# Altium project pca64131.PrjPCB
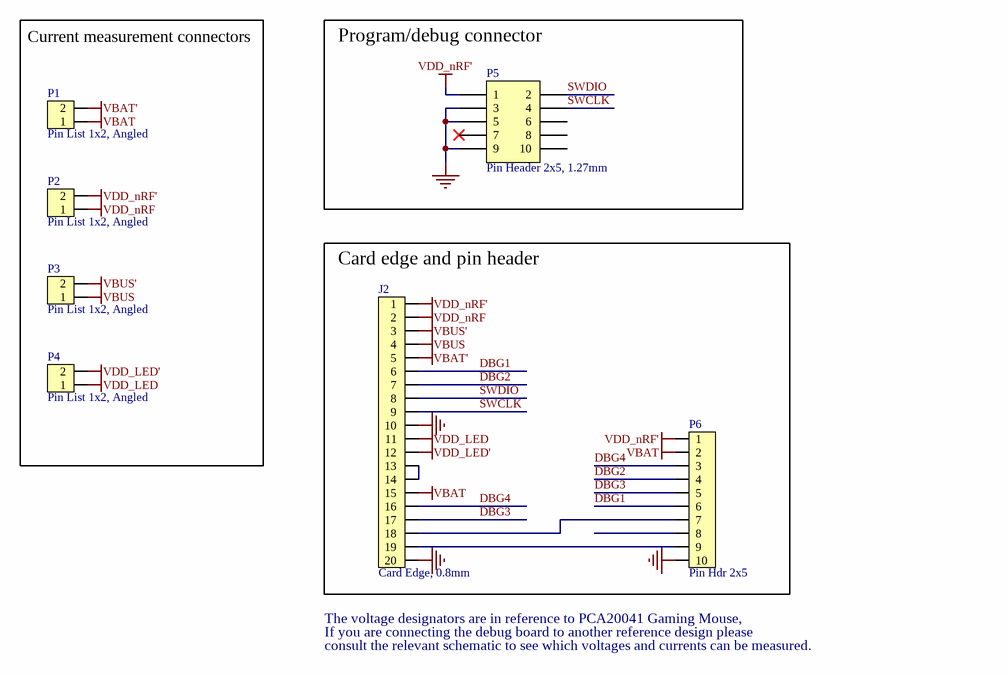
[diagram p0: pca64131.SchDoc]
SurfaceFinish: ENIG Gold; SoldermaskColor: Blue; SilkscreenColor: White; Revision: 0.4.1; ProjectNumber: 4456; ProjectName: nRF52 Desktop; PCBStackup: 2004; PCBRevision: 0017MASI; PCBNumber: 400391; PCAName: PCA64131; Organization: Nordic Semiconductor; NrOfLayers: 2; BoardTitle: nRF52 Desktop Debug Board; BoardThickness: 1.0mm; Author: RUBR/MASI
1 sheet, 7 parts. Net scope: global (net labels, ports and power ports of the same name join across sheets).
Board file: 400391.PcbDoc

## Sheet pca64131.SchDoc: =BoardTitle
size A4; Organization: Nordic Semiconductor; Revision: 0.4.1; SheetNumber: 1; SheetTotal: 1; Author: RUBR/MASI; CompanyName: Nordic Semiconductor; DrawnBy: RUBR/MASI

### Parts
J2  Card Edge, 0.8mm  [10056847-101LF Mating Board]
P1  Pin List 1x2, Angled  [LIST_ANG_1x2-SMD-2.54MM]
P2  Pin List 1x2, Angled  [LIST_ANG_1x2-SMD-2.54MM]
P3  Pin List 1x2, Angled  [LIST_ANG_1x2-SMD-2.54MM]
P4  Pin List 1x2, Angled  [LIST_ANG_1x2-SMD-2.54MM]
P5  Pin Header 2x5, 1.27mm  [HDR_2x5-SMD-1.27mm-K]
P6  Pin Hdr 2x5  [HDR_2x5-SMD]

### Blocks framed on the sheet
Current measurement connectors: P1-P4
Program/debug connector: P5
Card edge and pin header: J2 P6

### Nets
GND: J2.10 J2.20 P5.3 P5.5 P5.9 P6.10
VBAT: J2.15 P1.1 P6.2
VBAT': J2.5 P1.2
VBUS: J2.4 P3.1
VBUS': J2.3 P3.2
VDD_LED: J2.11 P4.1
VDD_LED': J2.12 P4.2
VDD_nRF: J2.2 P2.1
VDD_nRF': J2.1 P2.2 P5.1 P6.1
DBG1: J2.6 P6.6
DBG2: J2.7 P6.4
DBG3: J2.17 P6.5
DBG4: J2.16 P6.3
SWCLK: J2.9 P5.4
SWDIO: J2.8 P5.2
NetJ2_13: J2.13 J2.14
NetJ2_18: J2.18 P6.7
NetJ2_19: J2.19 P6.9

Not connected (* = marked no-connect by the designer): P5 6 7* 8 10; P6 8

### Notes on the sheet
- The voltage designators are in reference to PCA20041 Gaming Mouse,
- If you are connecting the debug board to another reference design please
- consult the relevant schematic to see which voltages and currents can be measured.

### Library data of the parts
J2 = 10056847-101LF Mating Board: 0.8mm pitch, dual edge, card edge connector; Artikkelnr Noca: N.A.
P1-P4 = Pin List Ang 1x2 SMD, 2.54mm: Pin List 1x2, 2.54mm (100mil), Right Angled, SMD; Manufacturer: W-CON; Manufacturer Part Number: 1125B-1102S0Z135R2; Part number IPS: N.A.; Artikkelnr Noca: 55010023
P5 = Pin Header 2x5 SMD, 1.27mm, KS: Pin Header 2x5, 1.27mm (50mil), SMD, Keying Shroud; Manufacturer: W-CON; Manufacturer Part Number: 3132-10MS0BK00R1; Part number IPS: N.A.; Artikkelnr Noca: 55010009
P6 = Pin Header 2x5 SMD: Pin Header 2x5, 2.54mm (100mil) SMD; Manufacturer: Molex; Part number IPS: N.A.; Artikkelnr Noca: 55019194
